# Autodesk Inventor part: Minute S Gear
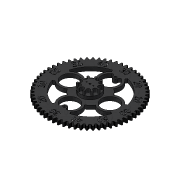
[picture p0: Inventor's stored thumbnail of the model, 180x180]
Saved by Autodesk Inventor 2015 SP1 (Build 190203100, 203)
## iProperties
Created: 2015-01
Part Number: Minute S Gear
Material: Generic
Document SubType Name: Modeling
Designer: Steve Brooks
Density: 1 g/cm^3
Appearance: Machined 02
Author: Steve Brooks
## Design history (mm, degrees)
sketch "Sketch1"
  geometry: L1 (-158.346, 58.118)-(-158.394, 58.136); L2 (-151.188, -78.566)-(-151.233, -78.589); L3 (-154.98, -70.615)-(-155.026, -70.636); L4 (-158.351, -62.477)-(-158.398, -62.495); L5 (-113.858, -127.219)-(-113.892, -127.257); L6 (-53.268, -162.203)-(-53.284, -162.252); L7 (148.645, -78.577)-(148.69, -78.6); L8 (139.845, 89.448)-(139.888, 89.476); L9 (90.374, 138.922)-(90.402, 138.965); L10 (97.634, 133.932)-(97.664, 133.973); L11 (111.32, 122.848)-(111.354, 122.886); L12 (104.622, 128.57)-(104.654, 128.609); L13 (118.769, -2.195)-(118.731, -2.161); L14 (166.194, 88.442)-(167.602, 90.044); L15 (167.602, 90.044)-(168.974, 91.706); L16 (168.974, 91.706)-(170.31, 93.425); L17 (170.31, 93.425)-(171.611, 95.197); L18 (171.611, 95.197)-(169.483, 98.884); L19 (169.483, 98.884)-(167.297, 98.643); L20 (167.297, 98.643)-(165.14, 98.345); L21 (165.14, 98.345)-(163.015, 97.988); L22 (163.015, 97.988)-(160.924, 97.57); L23 (160.924, 97.57)-(158.871, 97.086); L24 (158.871, 97.086)-(157.858, 96.819); L25 (157.858, 96.819)-(157.357, 96.678); L26 (157.357, 96.678)-(156.857, 96.533); L27 (156.857, 96.533)-(153.204, 102.159); L28 (153.204, 102.159)-(153.539, 102.556); L29 (153.539, 102.556)-(153.872, 102.957); L30 (153.872, 102.957)-(154.528, 103.773); L31 (154.528, 103.773)-(155.805, 105.453); L32 (155.805, 105.453)-(157.038, 107.193); L33 (157.038, 107.193)-(158.228, 108.989); L34 (158.228, 108.989)-(159.378, 110.837); L35 (159.378, 110.837)-(160.486, 112.737); L36 (160.486, 112.737)-(157.985, 116.181); L37 (157.985, 116.181)-(155.835, 115.713); L38 (155.835, 115.713)-(153.722, 115.191); L39 (153.722, 115.191)-(151.646, 114.614); L40 (151.646, 114.614)-(149.61, 113.979); L41 (149.61, 113.979)-(147.618, 113.284); L42 (147.618, 113.284)-(146.639, 112.912); L43 (146.639, 112.912)-(146.155, 112.72); L44 (146.155, 112.72)-(145.674, 112.523); L45 (145.674, 112.523)-(141.452, 117.736); L46 (141.452, 117.736)-(141.744, 118.166); L47 (141.744, 118.166)-(142.033, 118.6); L48 (142.033, 118.6)-(142.601, 119.48); L49 (142.601, 119.48)-(143.695, 121.284); L50 (143.695, 121.284)-(144.739, 123.143); L51 (144.739, 123.143)-(145.736, 125.054); L52 (145.736, 125.054)-(146.685, 127.013); L53 (146.685, 127.013)-(147.589, 129.018); L54 (147.589, 129.018)-(144.741, 132.181); L55 (144.741, 132.181)-(142.653, 131.491); L56 (142.653, 131.491)-(140.605, 130.752); L57 (140.605, 130.752)-(138.601, 129.961); L58 (138.601, 129.961)-(136.643, 129.117); L59 (136.643, 129.117)-(134.734, 128.216); L60 (134.734, 128.216)-(133.8, 127.744); L61 (133.8, 127.744)-(133.338, 127.502); L62 (133.338, 127.502)-(132.881, 127.256); L63 (132.881, 127.256)-(128.137, 132); L64 (128.137, 132)-(128.383, 132.458)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
  constraints: 2182 end point
extrude "Extrusion1" new body sketch "Sketch1" distance "d0" = 18; taper "d1" = 0 deg
sketch "Sketch3"
  geometry: L1 (0.84, 196.249)-(-3.416, 196.249) reference; L2 (-199.706, -0.04)-(-199.706, -4.297) reference; L3 (197.13, -4.297)-(197.131, -0.061) reference; L4 (-3.416, -200.586)-(0.84, -200.586) reference; L5 (-199.706, -0.04)-(-199.706, -4.297) reference; L6 (-3.416, -200.586)-(0.84, -200.586) reference; L7 (197.13, -4.297)-(197.131, -0.061) reference; L8 (166.194, 88.442)-(167.602, 90.044) reference; L9 (167.602, 90.044)-(168.974, 91.706) reference; L10 (168.974, 91.706)-(170.31, 93.425) reference; L11 (170.31, 93.425)-(171.611, 95.197) reference; L12 (171.611, 95.197)-(169.483, 98.884) reference; L13 (169.483, 98.884)-(167.297, 98.643) reference; L14 (167.297, 98.643)-(165.14, 98.345) reference; L15 (165.14, 98.345)-(163.015, 97.988) reference; L16 (163.015, 97.988)-(160.924, 97.57) reference; L17 (160.924, 97.57)-(158.871, 97.086) reference; L18 (158.871, 97.086)-(157.858, 96.819) reference; L19 (157.858, 96.819)-(157.357, 96.678) reference; L20 (157.357, 96.678)-(156.857, 96.533) reference; L21 (156.857, 96.533)-(153.204, 102.159) reference; L22 (153.204, 102.159)-(153.539, 102.556) reference; L23 (153.539, 102.556)-(153.872, 102.957) reference; L24 (153.872, 102.957)-(154.528, 103.773) reference; L25 (154.528, 103.773)-(155.805, 105.453) reference; L26 (155.805, 105.453)-(157.038, 107.193) reference; L27 (157.038, 107.193)-(158.228, 108.989) reference; L28 (158.228, 108.989)-(159.378, 110.837) reference; L29 (159.378, 110.837)-(160.486, 112.737) reference; L30 (160.486, 112.737)-(157.985, 116.181) reference; L31 (157.985, 116.181)-(155.835, 115.713) reference; L32 (155.835, 115.713)-(153.722, 115.191) reference; L33 (153.722, 115.191)-(151.646, 114.614) reference; L34 (151.646, 114.614)-(149.61, 113.979) reference; L35 (149.61, 113.979)-(147.618, 113.284) reference; L36 (147.618, 113.284)-(146.639, 112.912) reference; L37 (146.639, 112.912)-(146.155, 112.72) reference; L38 (146.155, 112.72)-(145.674, 112.523) reference; L39 (145.674, 112.523)-(141.452, 117.736) reference; L40 (141.452, 117.736)-(141.744, 118.166) reference; L41 (141.744, 118.166)-(142.033, 118.6) reference; L42 (142.033, 118.6)-(142.601, 119.48) reference; L43 (142.601, 119.48)-(143.695, 121.284) reference; L44 (143.695, 121.284)-(144.739, 123.143) reference; L45 (144.739, 123.143)-(145.736, 125.054) reference; L46 (145.736, 125.054)-(146.685, 127.013) reference; L47 (146.685, 127.013)-(147.589, 129.018) reference; L48 (147.589, 129.018)-(144.741, 132.181) reference; L49 (144.741, 132.181)-(142.653, 131.491) reference; L50 (142.653, 131.491)-(140.605, 130.752) reference; L51 (140.605, 130.752)-(138.601, 129.961) reference; L52 (138.601, 129.961)-(136.643, 129.117) reference; L53 (136.643, 129.117)-(134.734, 128.216) reference; L54 (134.734, 128.216)-(133.8, 127.744) reference; L55 (133.8, 127.744)-(133.338, 127.502) reference; L56 (133.338, 127.502)-(132.881, 127.256) reference; L57 (132.881, 127.256)-(128.137, 132) reference; L58 (128.137, 132)-(128.383, 132.458) reference; L59 (128.383, 132.458)-(128.624, 132.92) reference; L60 (128.624, 132.92)-(129.097, 133.854) reference; L61 (129.097, 133.854)-(129.997, 135.763) reference; L62 (129.997, 135.763)-(130.841, 137.721) reference; L63 (130.841, 137.721)-(131.632, 139.725) reference; L64 (131.632, 139.725)-(132.371, 141.772) reference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; 17 further points
  constraints: 9 midpoint, 2 horizontal alignment, 1 vertical alignment, 11 other
  dimensions: "d71" = 360 deg dimension on point (-1.288, -2.179) point (-43.288, -2.169) (derived); "d73" = 42 distance of point (-1.288, -2.179) point (-43.288, -2.169)
  node "Projected Loop1"
sketch "Sketch4"
  geometry: L1 (0.84, 196.249)-(-3.416, 196.249) reference; L2 (-199.706, -0.04)-(-199.706, -4.297) reference; L3 (-3.416, -200.586)-(0.84, -200.586) reference; C1 r 4 at (-1.288, -2.169); 5 further points
  constraints: 4 midpoint, 2 horizontal alignment, 2 vertical alignment, 1 centre point
  dimensions: "d81" = 8 diameter of C1
extrude "Extrusion3" cut sketch "Sketch4" stored distance "d22" = 10; taper "d23" = 0 deg
sketch "Sketch6"
  geometry: L1 (35.306, -130.625)-(40.306, -139.286); L2 (-38.855, -129.549)-(-43.855, -138.209); L3 (130.667, -35.16)-(139.328, -40.16); L4 (132.343, 28.811)-(141.003, 33.811); L5 (28.415, 132.437)-(33.415, 141.097); L6 (-32.256, 131.472)-(-37.256, 140.132); L7 (-131.294, 32.919)-(-139.954, 37.919); L8 (-129.509, -38.98)-(-138.169, -43.98); L9 (0.84, 196.249)-(-3.416, 196.249) reference; L10 (-199.706, -0.04)-(-199.706, -4.297) reference; L11 (-1.288, -2.169)-(-199.706, -2.169); L12 (-1.288, 196.249)-(-1.288, -200.586); L13 (-3.416, -200.586)-(0.84, -200.586) reference; C1 r 40 at (-1.288, -96.553); C2 r 40 at (93.097, -2.169); C3 r 40 at (-1.288, 92.216); C4 r 40 at (-95.673, -2.169); C5 r 4 at (-1.288, -2.169) reference; C6 r 4 at (-1.288, -2.169) reference; A1 r 50 centre (-1.288, -96.553) between (35.306, -130.625) and (-38.855, -129.549); A2 r 50 centre (93.097, -2.169) between (132.343, 28.811) and (130.667, -35.16); A3 r 50 centre (-1.288, 92.216) between (-32.256, 131.472) and (28.415, 132.437); A4 r 50 centre (-95.673, -2.169) between (-129.509, -38.98) and (-131.294, 32.919); A5 r 145 centre (0, 0) between (40.306, -139.286) and (139.328, -40.16); A6 r 145 centre (0, 0) between (141.003, 33.811) and (33.415, 141.097); A7 r 145 centre (0, 0) between (-37.256, 140.132) and (-139.954, 37.919); A8 r 145 centre (0, 0) between (-138.169, -43.98) and (-43.855, -138.209); A9 r 79.796 centre (0, 0) between (-67.093, -43.195) and (-42.158, -67.75); A10 r 79.796 centre (0, 0) between (-44.15, 66.469) and (-68.981, 40.111); A11 r 78.157 centre (0, 0) between (39.403, -67.498) and (64.941, -43.488); A12 r 78.157 centre (0, 0) between (66.896, 40.417) and (41.448, 66.262); A13 r 94.385 centre (-1.288, -2.169) between (-1.288, -96.553) and (-95.673, -2.169); 2 further points
  constraints: 36 point on circle, 20 end point, 17 centre point, 11 equal radius, 7 coincident, 7 equal length, 3 midpoint, 2 horizontal alignment, 2 vertical alignment, 1 perpendicular
  dimensions: "d32" = 10 distance of L1.start L1.end; "d36" = 10 radial gap between concentric circles of A1 C1; "d37" = 100 diameter of A1; "d82" = 30 deg angle of L11 L8; "d83" = 30 deg angle of L7 L11 (derived); "d84" = 30 deg angle of L6 L12 (derived); "d85" = 30 deg angle of L5 L12 (derived); "d86" = 30 deg angle of L11 L3 (derived); "d87" = 30 deg angle of L11 L4 (derived); "d88" = 30 deg angle of L1 L12 (derived); "d89" = 30 deg angle of L2 L12 (derived); "d90" = 145 radius of A8
extrude "Extrusion5" cut sketch "Sketch6" stored distance "d41" = 10; taper "d42" = 0 deg
sketch "Sketch9"
  geometry: L1 (9.712, -122.169)-(9.712, -135.011); L2 (-12.288, -135.011)-(-12.288, -122.169); L3 (9.712, 117.831)-(9.712, 130.674); L4 (-12.288, 130.674)-(-12.288, 117.831); C1 r 6 at (-1.288, -122.169); C2 r 6 at (-1.288, 117.831); C3 r 4 at (-1.288, -2.169) reference; A1 r 11 centre (-1.288, 117.831) between (-12.288, 117.831) and (9.712, 117.831); A2 r 11 centre (-1.288, -122.169) between (9.712, -122.169) and (-12.288, -122.169); A3 r 40 centre (-1.288, -96.553) between (-12.288, -135.011) and (9.712, -135.011); A4 r 50 centre (-1.288, -96.553) between (-42.158, -67.75) and (-38.855, -129.549) reference; A5 r 40 centre (-1.288, 92.216) between (-12.288, 130.674) and (9.712, 130.674) reference; 3 further points
  constraints: 10 point on circle, 9 end point, 5 centre point, 4 tangent, 4 vertical alignment, 3 coincident, 3 equal length, 1 equal radius, 1 point on line, 3 other
  dimensions: "d62" = 12 diameter of C1; "d63" = 12 diameter of C2; "d64" = 22 diameter of A1; "d91" = 240 distance of C2.centre A2.centre; "d92" = 120 distance of C3.centre A2.centre (derived)
extrude "Extrusion6" join sketch "Sketch9" stored distance "d66" = 10; taper "d67" = 0 deg
hole "Hole3" sketch "Sketch3" diameter "d74" = 8; stored, may be unused: countersink angle "d78" = 90 deg, drill point angle "d80" = 118 deg; dims "d75" = 6, "d76" = 4, "d77" = 2, "d79" = 8
fillet "Fillet2" dims "d93" = 8
sketch "Sketch10"
  geometry: A1 r 4 centre (-1.288, -2.179) between (-5.288, -2.174) and (2.712, -2.174) reference; 2 further points
  constraints: 2 horizontal alignment
  dimensions: "d94" = 31.75 distance of point (14.587, -2.179) point (-17.163, -2.179); "d95" = 15.875 distance of A1.centre point (-17.163, -2.179) (derived)
hole "Hole4" sketch "Sketch10" at (-17.163, -2.179), (14.587, -2.179) diameter "d96" = 1; stored, may be unused: countersink angle "d100" = 90 deg, drill point angle "d102" = 118 deg; dims "d97" = 6, "d98" = 4, "d99" = 2, "d101" = 8
sketch "Sketch12"
  geometry: L1 (197.13, -4.297)-(197.131, -0.061) reference; L2 (177.833, 11.673)-(177.831, -16.029); L3 (177.831, -16.029)-(151.798, -16.028); L4 (151.798, -16.028)-(151.799, 11.675); L5 (151.799, 11.675)-(177.833, 11.673); L6 (124.524, 86.614)-(146.599, 99.358); L7 (146.599, 99.358)-(160.587, 75.128); L8 (160.587, 75.128)-(138.512, 62.384); L9 (138.512, 62.384)-(124.524, 86.614); L10 (64.708, 138.572)-(75.982, 158.095); L11 (75.982, 158.095)-(98.876, 144.876); L12 (98.876, 144.876)-(87.603, 125.352); L13 (87.603, 125.352)-(64.708, 138.572); L14 (-15.24, 150.91)-(-15.239, 176.943); L15 (-15.239, 176.943)-(12.66, 176.942); L16 (12.66, 176.942)-(12.659, 150.908); L17 (12.659, 150.908)-(-15.24, 150.91); L18 (-125.115, 186.089)-(-66.337, 84.271); L19 (-66.337, 84.271)-(-43.639, 97.374); L20 (-43.639, 97.374)-(-102.416, 199.192); L21 (-102.416, 199.192)-(-125.115, 186.089); L22 (-140.842, 63.81)-(-162.238, 76.165); L23 (-162.238, 76.165)-(-149.611, 98.034); L24 (-149.611, 98.034)-(-128.214, 85.679); L25 (-128.214, 85.679)-(-140.842, 63.81); L26 (-154.494, -14.513)-(-180.527, -14.512); L27 (-180.527, -14.512)-(-180.526, 10.152); L28 (-180.526, 10.152)-(-154.492, 10.151); L29 (-154.492, 10.151)-(-154.494, -14.513); L30 (-339.673, -134.689)-(-339.673, -108.656); L31 (-339.673, -108.656)-(-302.153, -108.656); L32 (-302.153, -108.656)-(-302.153, -134.689); L33 (-302.153, -134.689)-(-339.673, -134.689); L34 (-127.364, -90.099)-(-149.91, -103.114); L35 (-149.91, -103.114)-(-163.009, -80.422); L36 (-163.009, -80.422)-(-140.463, -67.407); L37 (-140.463, -67.407)-(-127.364, -90.099); L38 (-66.033, -141.581)-(-79.051, -164.126); L39 (-79.051, -164.126)-(-102.654, -150.497); L40 (-102.654, -150.497)-(-89.637, -127.952); L41 (-89.637, -127.952)-(-66.033, -141.581); L42 (11.3, -183.788)-(11.301, -152.957); L43 (11.301, -152.957)-(-13.872, -152.956); L44 (-13.872, -152.956)-(-13.874, -183.786); L45 (-13.874, -183.786)-(11.3, -183.788); L46 (102.57, -154.911)-(84.49, -123.592); L47 (84.49, -123.592)-(60.974, -137.168); L48 (60.974, -137.168)-(79.053, -168.486); L49 (79.053, -168.486)-(102.57, -154.911); L50 (138.463, -66.701)-(160.629, -79.5); L51 (160.629, -79.5)-(146.633, -103.74); L52 (146.633, -103.74)-(124.466, -90.941); L53 (124.466, -90.941)-(138.463, -66.701); L54 (173.923, 61.496)-(171.519, 67.759) reference; L55 (172.721, 64.627)-(135.921, 50.502); L56 (197.13, -2.179)-(-1.288, -2.169); L57 (170.547, 97.03)-(-1.293, -2.17); L58 (97.921, 169.656)-(-1.297, -2.174); L59 (-1.288, 196.239)-(-1.298, -2.179); L60 (-100.497, 169.656)-(-1.297, -2.184); L61 (-173.123, 97.03)-(-1.293, -2.188); L62 (-199.706, -2.179)-(-1.288, -2.189); L63 (-173.123, -101.388)-(-1.283, -2.188); L64 (-100.497, -174.014)-(-1.279, -2.184)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; A1 r 4 centre (-1.288, -2.179) between (-5.288, -2.174) and (2.712, -2.174) reference; A2 r 4 centre (-1.288, -2.169) between (2.712, -2.174) and (-5.288, -2.174) reference; A3 r 145 centre (0, 0) between (141.003, 33.811) and (33.415, 141.097) reference; 38 further points
  constraints: 39 midpoint, 26 end point, 24 point on line, 1 coincident, 1 point on circle, 78 other
  dimensions: "d117" = 360 deg dimension on A1.centre L56.start (derived)
extrude "Extrusion7" cut sketch "Sketch12" distance "d119" = 4; taper "d120" = 0 deg
sketch "Sketch13"
  geometry: L1 (-1.288, -2.169)-(-35.37, 22.595); L2 (-1.291, -2.169)-(-41.357, 10.851); L3 (-1.294, -2.171)-(-43.422, -2.169); L4 (-1.296, -2.173)-(-41.363, -15.19); L5 (-1.298, -2.176)-(-35.381, -26.937); L6 (-1.298, -2.179)-(-26.062, -36.26); L7 (-1.298, -2.182)-(-14.318, -42.248); L8 (-1.296, -2.185)-(-1.298, -44.313); L9 (-1.294, -2.187)-(11.723, -42.254); L10 (-1.291, -2.189)-(23.47, -36.272); L11 (-1.288, -2.189)-(32.793, -26.953); L12 (-1.285, -2.189)-(38.781, -15.208); L13 (-1.282, -2.187)-(40.846, -2.189); L14 (-1.28, -2.185)-(38.787, 10.832); L15 (-1.278, -2.182)-(32.805, 22.579); L16 (-1.278, -2.179)-(23.486, 31.903); L17 (-1.278, -2.176)-(11.741, 37.89); L18 (-1.28, -2.173)-(-1.278, 39.955); L19 (-1.282, -2.171)-(-14.299, 37.896); L20 (-1.285, -2.169)-(-26.046, 31.914); C1 r 0.5 at (-17.163, -2.179) reference; C2 r 0.5 at (14.587, -2.179) reference; C3 r 4 at (-35.273, -26.858) reference; C4 r 4 at (-43.288, -2.169) reference; C5 r 28 at (-1.288, -2.169); A1 r 4 centre (-1.288, -2.179) between (-5.288, -2.174) and (2.712, -2.174) reference; A2 r 4 centre (-1.288, -2.169) between (2.712, -2.174) and (-5.288, -2.174) reference; A3 r 4.5 centre (-35.273, -26.858) between (-35.555, -22.366) and (-31.089, -28.514); A4 r 4.5 centre (-14.299, -42.137) between (-17.159, -38.662) and (-9.933, -41.048); A5 r 4.5 centre (11.683, -42.218) between (7.324, -41.101) and (14.607, -38.797); A6 r 4.5 centre (32.806, -26.994) between (28.636, -28.685) and (33.196, -22.511); A7 r 4.5 centre (40.947, -2.205) between (38.603, -6.047) and (38.642, 1.66); A8 r 4.5 centre (32.905, 22.652) between (33.301, 18.169) and (28.821, 24.542); A9 r 4.5 centre (11.761, 37.994) between (14.724, 34.606) and (7.382, 36.957); A10 r 4.5 centre (-14.334, 37.928) between (-9.949, 36.914) and (-17.235, 34.489); A11 r 4.5 centre (-35.37, 22.595) between (-31.207, 24.305) and (-35.709, 18.108); A12 r 4.5 centre (-43.354, -2.209) between (-41.011, 1.634) and (-40.922, -5.995); A13 r 8.9 centre (-22.974, 27.686) between (-31.207, 24.305) and (-17.235, 34.489); A14 r 8.9 centre (-36.379, 9.233) between (-41.011, 1.634) and (-35.709, 18.108); A15 r 8.9 centre (-36.112, -13.484) between (-35.555, -22.366) and (-40.922, -5.995); A16 r 8.9 centre (-22.814, -31.79) between (-17.159, -38.662) and (-31.089, -28.514); A17 r 8.9 centre (-1.298, -38.893) between (7.324, -41.101) and (-9.933, -41.048); A18 r 8.9 centre (20.388, -32.03) between (28.636, -28.685) and (14.607, -38.797); A19 r 8.9 centre (33.967, -13.644) between (38.603, -6.047) and (33.196, -22.511); A20 r 8.9 centre (34.084, 9.304) between (33.301, 18.169) and (38.642, 1.66); A21 r 8.9 centre (20.582, 27.906) between (14.724, 34.606) and (28.821, 24.542); A22 r 8.9 centre (-1.278, 34.908) between (-9.949, 36.914) and (7.382, 36.957); 2 further points
  constraints: 41 point on circle, 40 end point, 21 centre point, 20 tangent, 18 equal radius, 12 point on line, 3 coincident, 1 horizontal alignment, 74 other
  dimensions: "d125" = 9 diameter of A5; "d126" = 56 diameter of C5; "d129" = 360 deg dimension on A1.centre L1.start (derived); "d134" = 8.9 radius of A19
extrude "Extrusion8" new body sketch "Sketch13" distance "d135" = 33; taper "d136" = 0 deg
sketch "Sketch14"
  geometry: C1 r 46.729 at (-1.288, -2.169)
  constraints: 1 centre point
extrude "Extrusion9" new body sketch "Sketch14" distance "d137" = 15; taper "d138" = 0 deg
sketch "Sketch15"
  geometry: A1 r 4 centre (0, 0) between (4, -0.005) and (-4, -0.005) reference; A2 r 4 centre (0, -0.01) between (-4, -0.005) and (4, -0.005) reference; A3 r 8.9 centre (21.87, 30.075) between (16.012, 36.775) and (30.11, 26.71) reference; A4 r 4.5 centre (13.05, 40.162) between (16.012, 36.775) and (8.67, 39.126) reference; A5 r 8.9 centre (0.01, 37.076) between (-8.661, 39.082) and (8.67, 39.126) reference; A6 r 4.5 centre (-13.045, 40.097) between (-8.661, 39.082) and (-15.947, 36.657) reference; A7 r 8.9 centre (-21.686, 29.855) between (-29.919, 26.473) and (-15.947, 36.657) reference; A8 r 4.5 centre (-34.081, 24.763) between (-29.919, 26.473) and (-34.42, 20.276) reference; A9 r 8.9 centre (-35.091, 11.402) between (-39.723, 3.802) and (-34.42, 20.276) reference; A10 r 4.5 centre (-42.065, -0.04) between (-39.723, 3.802) and (-39.634, -3.827) reference; A11 r 8.9 centre (-34.824, -11.315) between (-34.267, -20.198) and (-39.634, -3.827) reference; A12 r 4.5 centre (-33.985, -24.689) between (-34.267, -20.198) and (-29.801, -26.345) reference; A13 r 8.9 centre (-21.526, -29.621) between (-15.87, -36.494) and (-29.801, -26.345) reference; A14 r 4.5 centre (-13.011, -39.968) between (-15.87, -36.494) and (-8.645, -38.879) reference; A15 r 8.9 centre (-0.01, -36.724) between (8.612, -38.933) and (-8.645, -38.879) reference; A16 r 4.5 centre (12.971, -40.049) between (8.612, -38.933) and (15.895, -36.628) reference; A17 r 8.9 centre (21.676, -29.862) between (29.924, -26.517) and (15.895, -36.628) reference; A18 r 4.5 centre (34.094, -24.825) between (29.924, -26.517) and (34.484, -20.342) reference; A19 r 8.9 centre (35.255, -11.476) between (39.891, -3.878) and (34.484, -20.342) reference; A20 r 4.5 centre (42.235, -0.037) between (39.891, -3.878) and (39.93, 3.828) reference; A21 r 8.9 centre (35.372, 11.472) between (34.589, 20.338) and (39.93, 3.828) reference; A22 r 4.5 centre (34.194, 24.821) between (34.589, 20.338) and (30.11, 26.71) reference; 1 further point
extrude "Extrusion10" cut sketch "Sketch15" stored distance "d139" = 6; taper "d140" = 0 deg
sketch "Sketch16"
  geometry: C1 r 0.5 at (17.163, -2.179) reference; C2 r 0.5 at (-14.587, -2.179) reference; C3 r 2.5 at (-14.587, -2.179); C4 r 2.5 at (17.163, -2.179)
  constraints: 2 centre point, 2 coincident, 1 equal radius
  dimensions: "d141" = 5 diameter of C3
extrude "Extrusion11" cut sketch "Sketch16" stored distance "d142" = 6; taper "d143" = 0 deg
sketch "Sketch17"
  geometry: C1 r 2.5 at (17.163, -2.179) reference; C2 r 2.5 at (-14.587, -2.179) reference; 1 further point
extrude "Extrusion12" cut sketch "Sketch17" stored distance "d144" = 6; taper "d145" = 0 deg
sketch "Sketch18"
  geometry: C1 r 2.5 at (15.875, -0.01) reference; C2 r 2.5 at (-15.875, -0.01) reference; 1 further point
extrude "Extrusion13" cut sketch "Sketch18" stored distance "d146" = 6; taper "d147" = 0 deg
body "Solid1"
body "Solid2"
body "Solid3"
node "Projected Loop2"
